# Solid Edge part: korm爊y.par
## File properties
Author: morva
Template: iso metric part.par
Last saved by: morva
Revision: 14
Application: Solid Edge
Density: 2712.000 kg/m^3
Accuracy: 0.990
Username: morva
Material: Aluminum, 6061-T6
Face Style: Aluminum
Fill Style: ANSI38(Aluminum)
Virtual Style: Polished aluminum
Grouping: Metals\Aluminium Alloys
LibraryName: Materials
Coef. of Thermal Exp: 2.3e-05
Thermal Conductivity: 180.0
Specific Heat: 920.0
Modulus of Elasticity: 68947570000.0
Poisson's Ratio: 0.33
Yield Stress: 275790280.0
Ultimate Stress: 310264065.0
Elongation: 0.0
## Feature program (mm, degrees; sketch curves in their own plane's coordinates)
swept protrusion "SweptProtrusion_1"
swept protrusion "SweptProtrusion_2"
swept cutout "SweptCutout_1"
swept cutout "SweptCutout_2"
mirror "unnamed Mirror 1" of "SweptCutout_2", "SweptCutout_1", "SweptProtrusion_2", "SweptProtrusion_1"
pattern "unnamed Pattern 1"
thread "Thread_4"  ThreadDepth = 45 mm
thread "Thread_5"  ThreadDepth = 15 mm
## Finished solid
Body 1: solid body, 19 faces, 28 edges, 16 vertices.
  Faces by surface: cylinder 16, plane 3
  Edges by curve: ellipse 16, circle 8, intersection 4
Bounding box of the edges (mm): 915.000 x 30.000 x 600.000, from (-15, -15, 0) to (900, 15, 600).
Cylindrical faces by radius (mm): R12 x7, R15 x9
Planar faces by outward normal: +x 1, +z 1, -z 1
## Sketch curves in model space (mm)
line (0, 0, 200) -> (0, 0, 300)
line (0, 0, 0) -> (0, 0, 200)
line (100, 0, 300) -> (900, 0, 300)
line (0, 0, 200) -> (100, 0, 300)
circle centre (0, 0, 0) radius 12
circle centre (0, 0, 0) radius 15
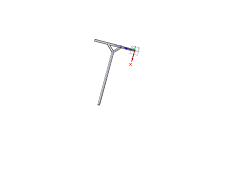
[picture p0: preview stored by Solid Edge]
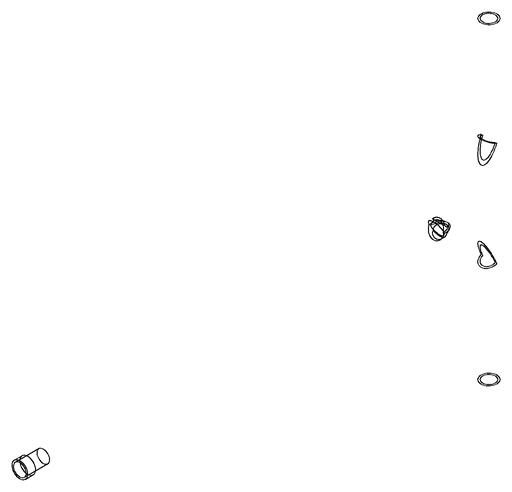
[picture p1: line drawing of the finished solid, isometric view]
